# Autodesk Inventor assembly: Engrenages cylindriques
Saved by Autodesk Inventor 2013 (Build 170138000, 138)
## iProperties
Created: 2011-10
Part Number: Engrenages cylindriques
Document SubType Name: Assembly
Designer: Laur
ClientObjectVersion: 1
Author: Laur
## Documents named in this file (2)
- D:\_an13-14\FORMULAIRE_2014\Sujet E4 Poissy 2014\Modélisation_7970_shimano_2014\Mobile intermédiaire 37 dents m0,25 - 10 dents m0,3\Design Accelerator\Engrenages cylindriques3.iam
- D:\_an13-14\FORMULAIRE_2014\Sujet E4 Poissy 2014\Modélisation_7970_shimano_2014\Mobile intermédiaire 37 dents m0,25 - 10 dents m0,3\Design Accelerator\Engrenage cylindrique21.ipt
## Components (1 placed, 1 different names)
1. Engrenage cylindrique2:1
